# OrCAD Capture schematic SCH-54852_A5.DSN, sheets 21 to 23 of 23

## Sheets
21 C-16 EXPI/IMU/ADC: size C
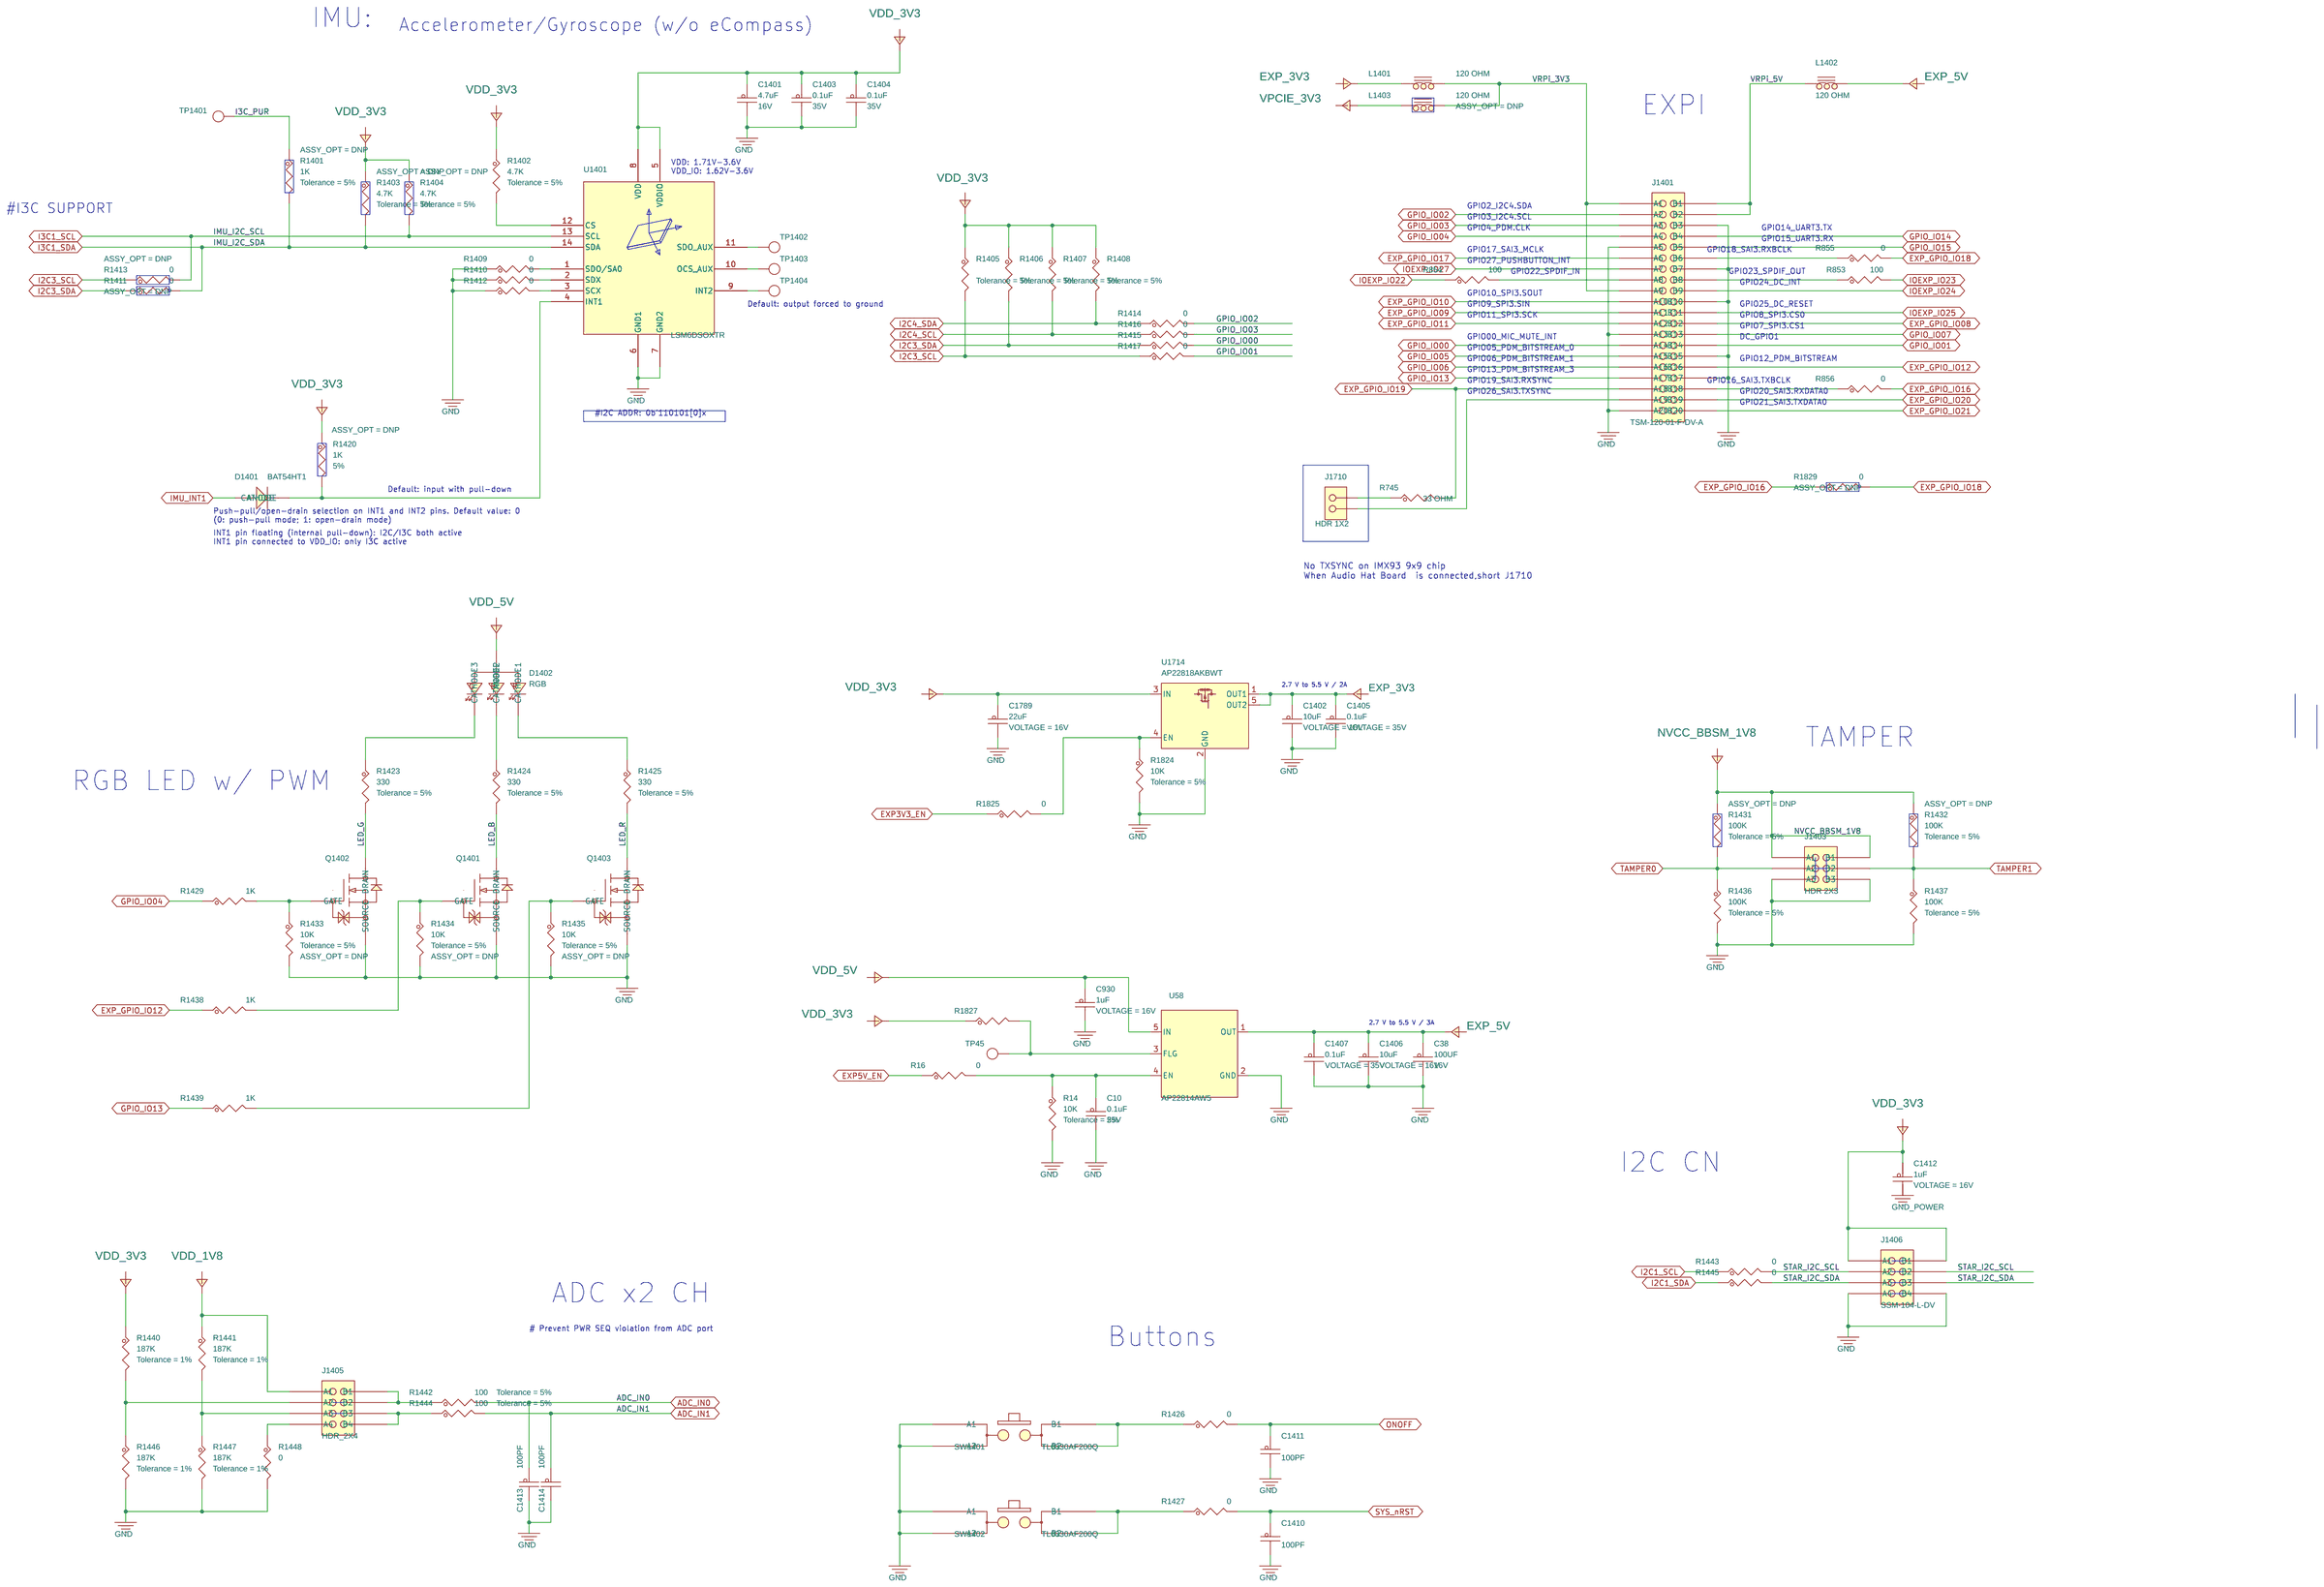
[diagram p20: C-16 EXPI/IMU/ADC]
22 C-08 eMMC/MicroSD: size C
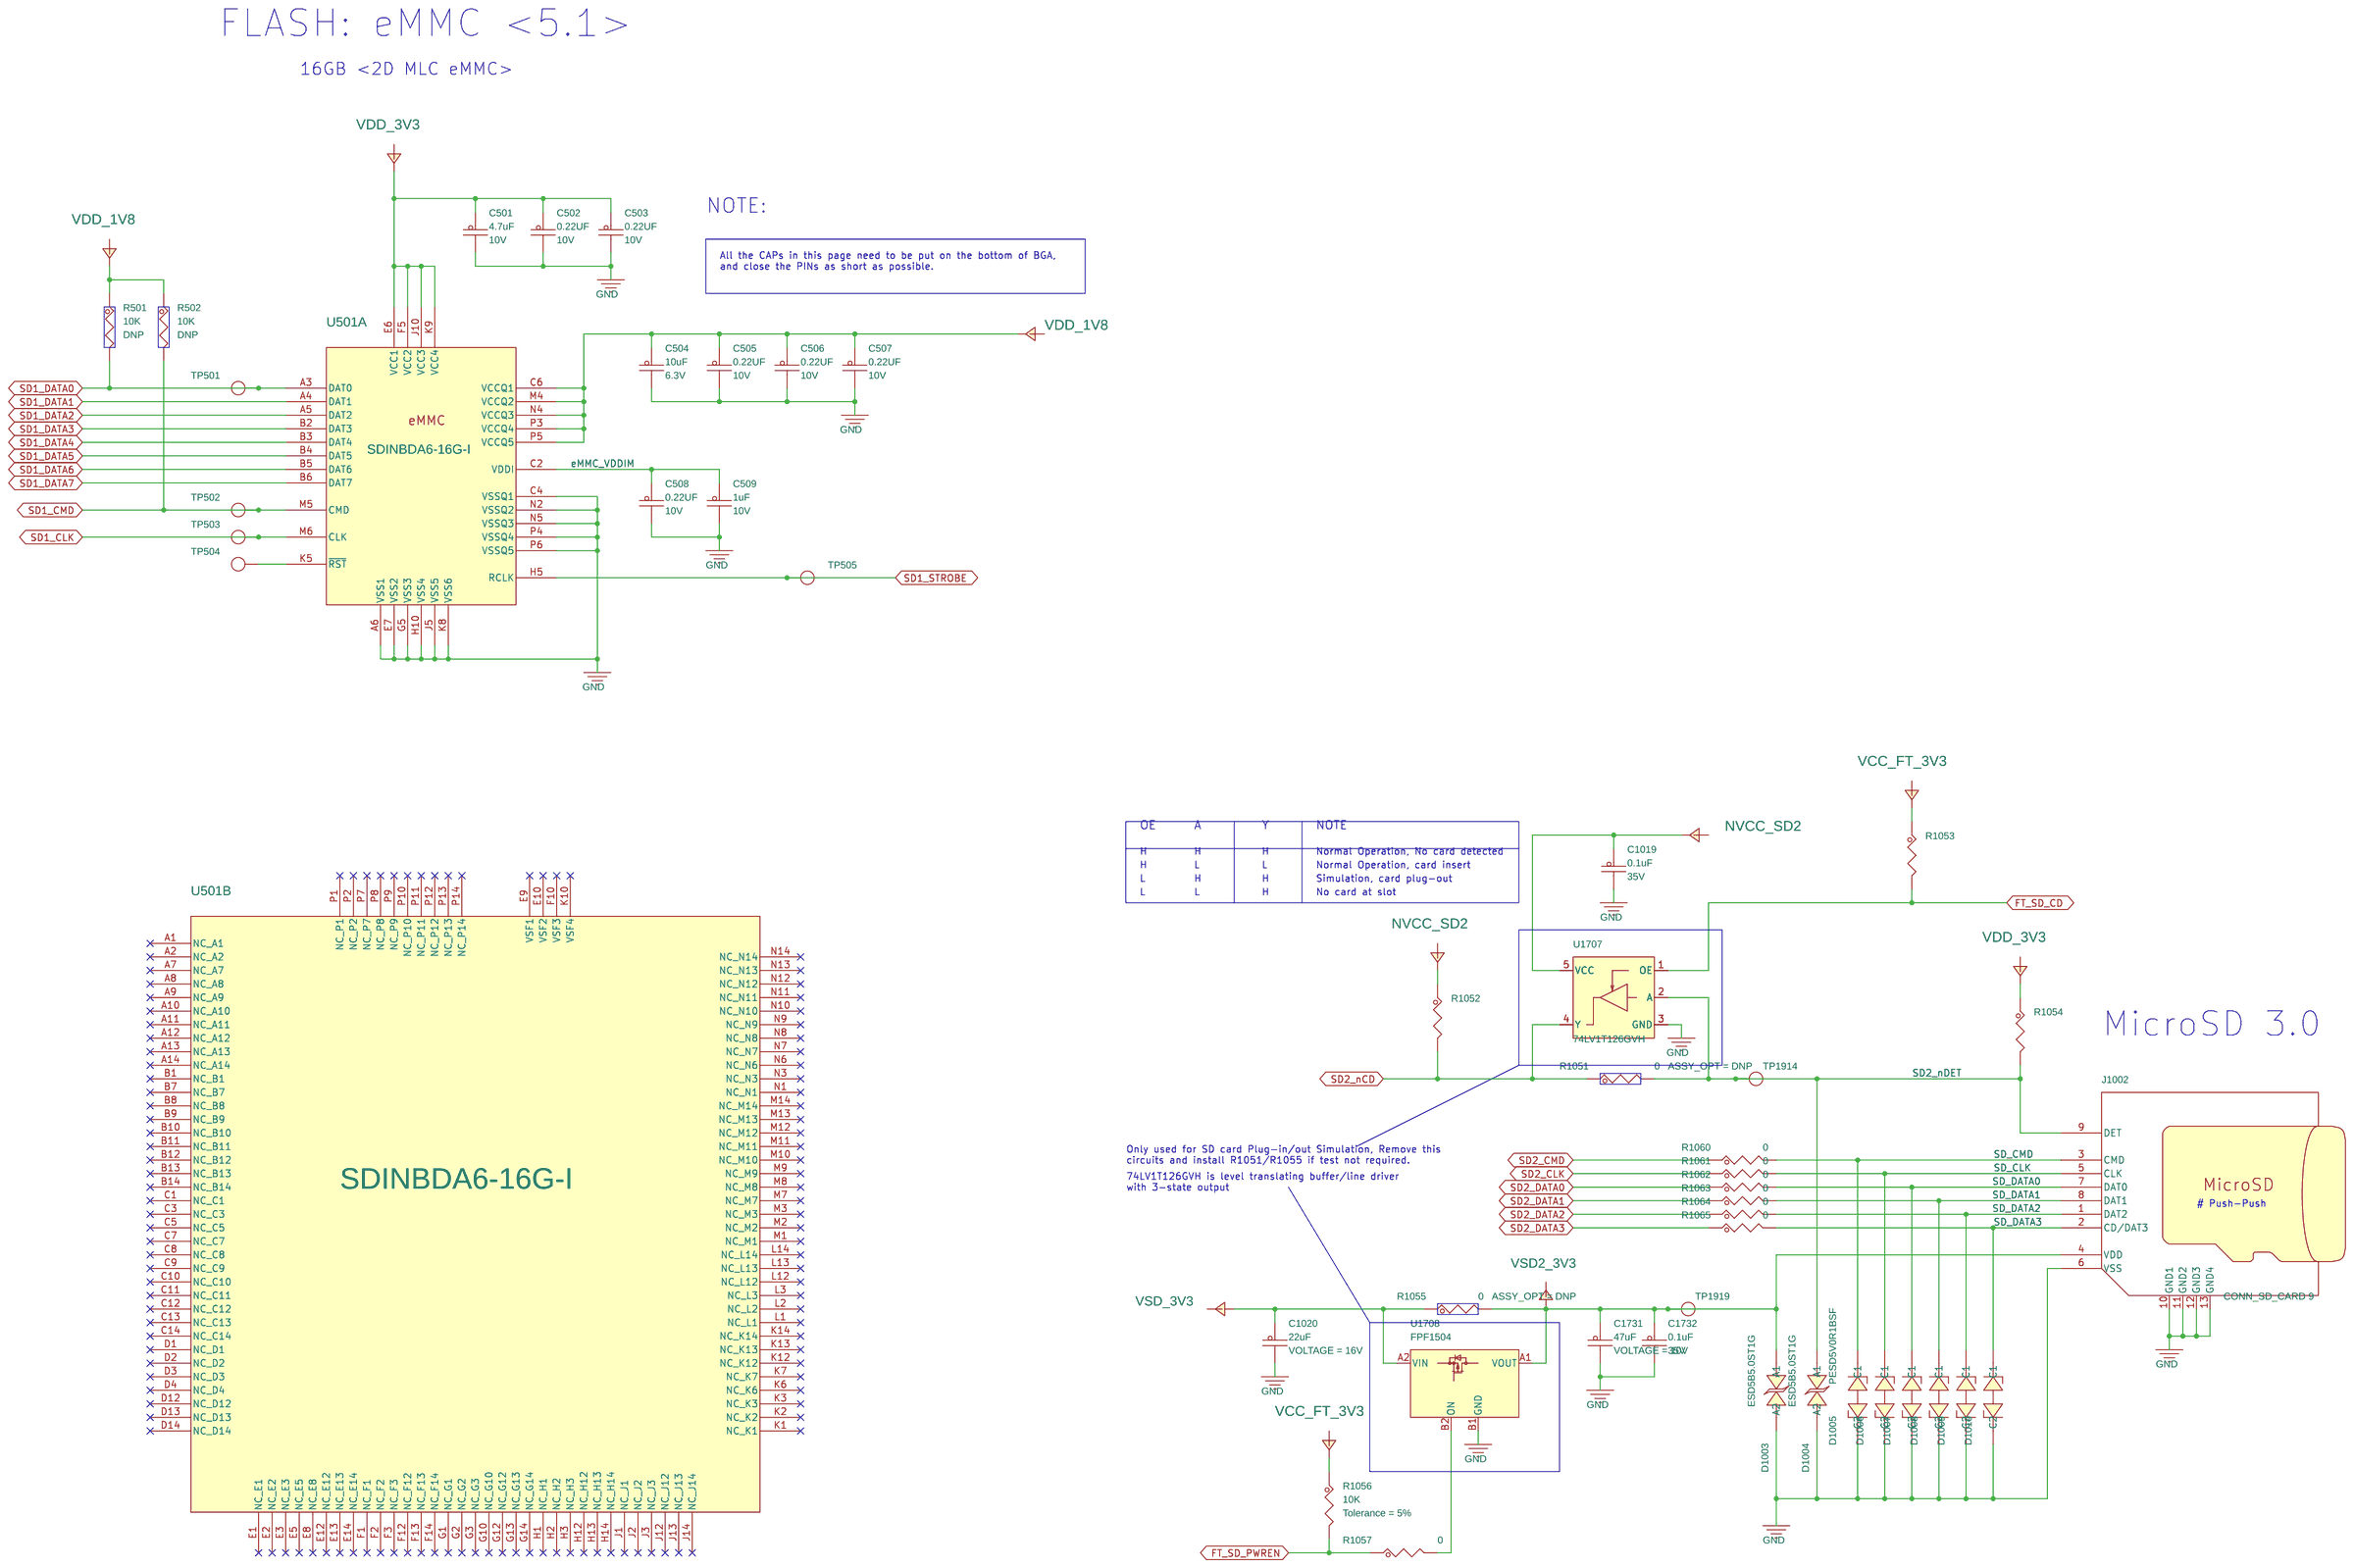
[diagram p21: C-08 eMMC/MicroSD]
23 C-19 BOOT CFG/PDM: size C
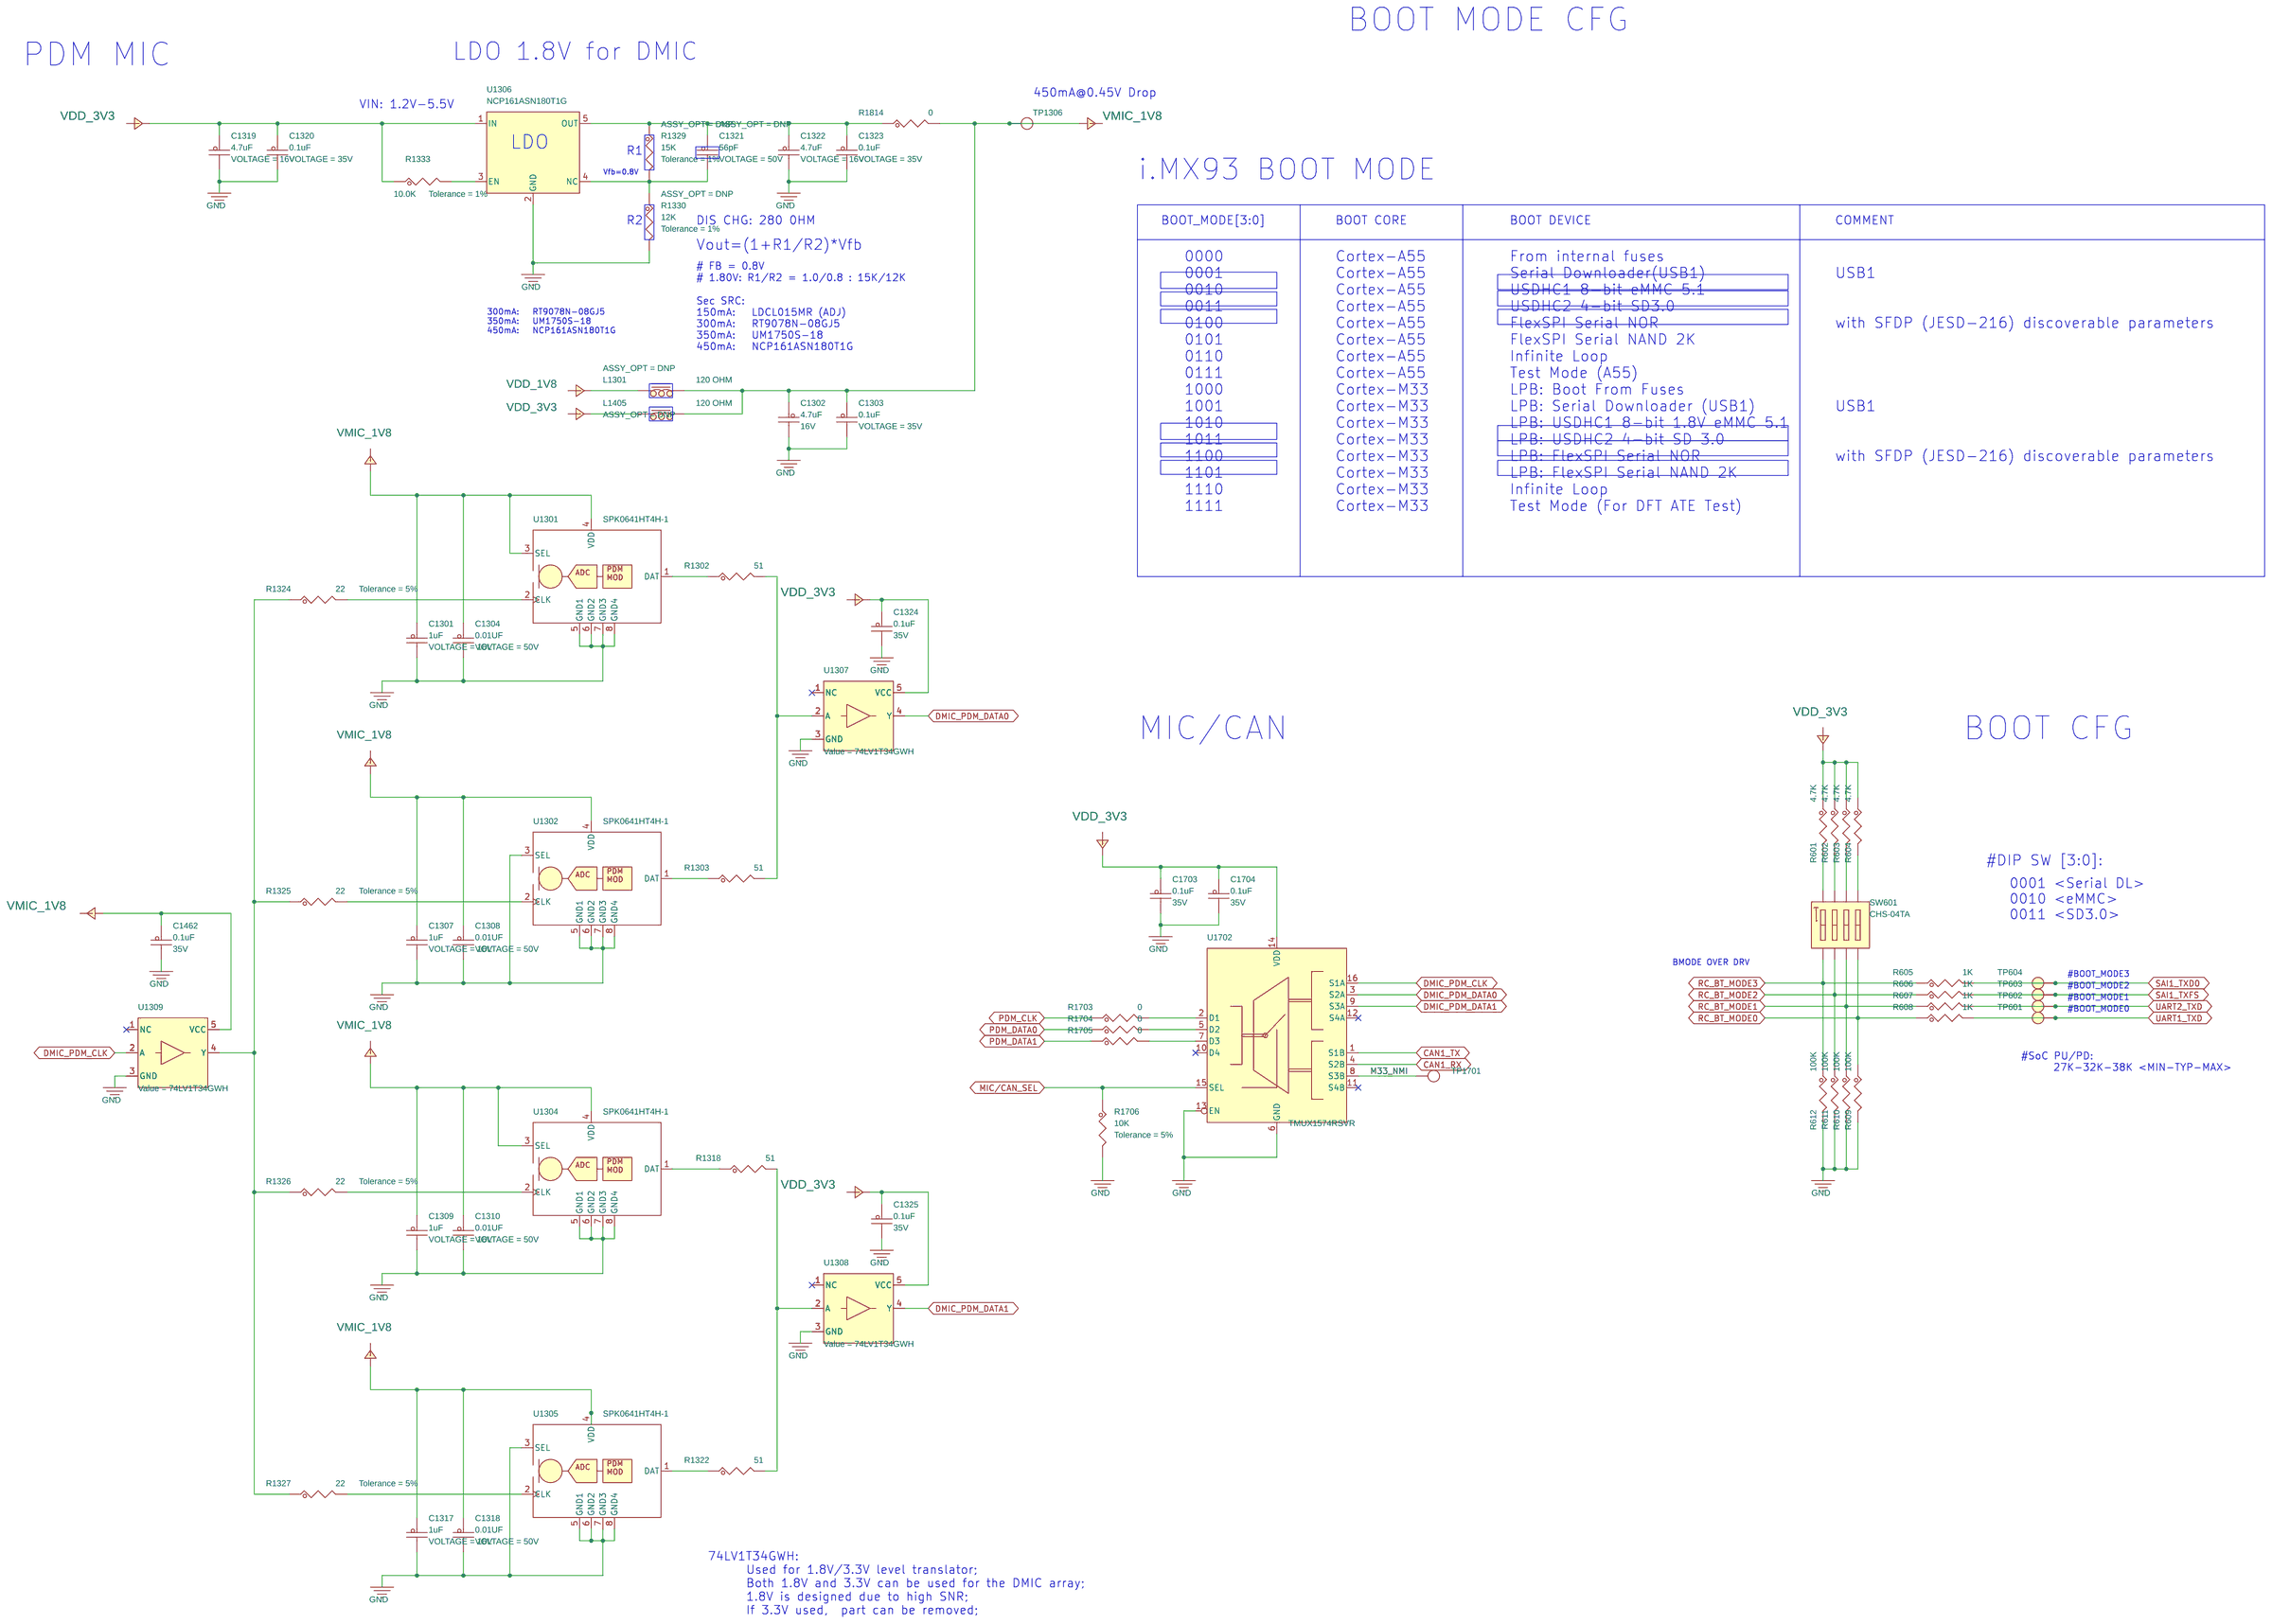
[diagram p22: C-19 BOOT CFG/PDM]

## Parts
sheet C-08 eMMC/MicroSD
C501  4.7uF  [cc0402_tol0p15]
C502  0.22UF  [0201_CC]
C503  0.22UF  [0201_CC]
C504  10uF  [0402_CC]
C505  0.22UF  [0201_CC]
C506  0.22UF  [0201_CC]
C507  0.22UF  [0201_CC]
C508  0.22UF  [0201_CC]
C509  1uF  [0201_CC]
C1019  0.1uF  [CC0402_25]
C1020  22uF  [CC0805_OV]
C1731  47uF  [0805_CC]
C1732  0.1uF  [CC0402_25]
D1003  ESD5B5.0ST1G  [diode2_sod523]
D1004  ESD5B5.0ST1G  [diode2_sod523]
D1005  PESD5V0R1BSF  [dsn0603-2]
D1006  PESD5V0R1BSF  [dsn0603-2]
D1007  PESD5V0R1BSF  [dsn0603-2]
D1008  PESD5V0R1BSF  [dsn0603-2]
D1009  PESD5V0R1BSF  [dsn0603-2]
D1010  PESD5V0R1BSF  [dsn0603-2]
J1002  CONN_SD_CARD 9  [con9_sdcard_1p1mm]
R501  10K  [0402_CC]
R502  10K  [0402_CC]
R1051  0  [0402_CC]
R1052  10K  [0402_CC]
R1053  10K  [0402_CC]
R1054  10K  [0402_CC]
R1055  0  [0603_CC]
R1056  10K  [0402_CC]
R1057  0  [0402_CC]
R1060  0  [0402_CC]
R1061  0  [0402_CC]
R1062  0  [0402_CC]
R1063  0  [0402_CC]
R1064  0  [0402_CC]
R1065  0  [0402_CC]
TP501  TPAD_020  [tpad_020]
TP502  TPAD_020  [tpad_020]
TP503  TPAD_020  [tpad_020]
TP504  TPAD_015  [TPAD_015]
TP505  TPAD_020  [tpad_020]
TP1914  TPAD_050  [TPAD_050]
TP1919  TPAD_050  [TPAD_050]
U501  SDINBDA6-16G-I  [fbga153_0p5_11p5x13]  (sections A,B)
U1707  74LV1T126GVH  [sot753_5p_1p7x3p1mm]
U1708  FPF1504  [wlcsp4_0p5_0p99x0P99]
sheet C-16 EXPI/IMU/ADC
C10  0.1uF  [0402_CC]
C38  100UF  [1210_CC]
C930  1uF  [CC0402_25]
C1401  4.7uF  [CC0603_OV]
C1402  10uF  [CC0603_OV]
C1403  0.1uF  [CC0402_25]
C1404  0.1uF  [CC0402_25]
C1405  0.1uF  [CC0402_25]
C1406  10uF  [CC0603_OV]
C1407  0.1uF  [CC0402_25]
C1410  100PF  [CC0402_25]
C1411  100PF  [CC0402_25]
C1412  1uF  [CC0402_25]
C1413  100PF  [CC0402_25]
C1414  100PF  [CC0402_25]
C1789  22uF  [CC0805_OV]
D1401  BAT54HT1  [SOD323]
D1402  RGB  [led4_3p4x3_sm]
J1401  TSM-120-01-F-DV-A  [hdr220_tsm_a_sm]
J1403  HDR 2X3  [hdr203_tmm_210h]
J1405  HDR_2X4  [HDR204_TMM_SM]
J1406  SSM-104-L-DV  [con_2x4_skt_100_sm]
J1710  HDR 1X2  [hdr102_tmm]
L1401  120 OHM  [IND_0603]
L1402  120 OHM  [IND_0603]
L1403  120 OHM  [IND_0603]
Q1401  NX3008NBKW,115  [sc70_3]
Q1402  NX3008NBKW,115  [sc70_3]
Q1403  NX3008NBKW,115  [sc70_3]
R14  10K  [0402_CC]
R16  0  [0402_CC]
R745  33 OHM  [RC0402_25]
R853  100  [RC0402_25]
R854  100  [RC0402_25]
R855  0  [0402_CC]
R856  0  [0402_CC]
R1401  1K  [0402_CC]
R1402  4.7K  [RC0402_25]
R1403  4.7K  [RC0402_25]
R1404  4.7K  [RC0402_25]
R1405  2.2K  [0402_CC]
R1406  2.2K  [0402_CC]
R1407  2.2K  [0402_CC]
R1408  2.2K  [0402_CC]
R1409  0  [0402_CC]
R1410  0  [0402_CC]
R1411  0  [0402_CC]
R1412  0  [0402_CC]
R1413  0  [0402_CC]
R1414  0  [0402_CC]
R1415  0  [0402_CC]
R1416  0  [0402_CC]
R1417  0  [0402_CC]
R1420  1K  [0402_CC]
R1423  330  [RC0402_25]
R1424  330  [RC0402_25]
R1425  330  [RC0402_25]
R1426  0  [0402_CC]
R1427  0  [0402_CC]
R1429  1K  [0402_CC]
R1431  100K  [0402_CC]
R1432  100K  [0402_CC]
R1433  10K  [0402_CC]
R1434  10K  [0402_CC]
R1435  10K  [0402_CC]
R1436  100K  [0402_CC]
R1437  100K  [0402_CC]
R1438  1K  [0402_CC]
R1439  1K  [0402_CC]
R1440  187K  [0402_CC]
R1441  187K  [0402_CC]
R1442  100  [RC0402_25]
R1443  0  [0402_CC]
R1444  100  [RC0402_25]
R1445  0  [0402_CC]
R1446  187K  [0402_CC]
R1447  187K  [0402_CC]
R1448  0  [0402_CC]
R1824  10K  [0402_CC]
R1825  0  [0402_CC]
R1827  10K  [0402_CC]
R1829  0  [0402_CC]
SW1401  TL6330AF200Q  [sw4_spst_4p6x2p8_sm]
SW1402  TL6330AF200Q  [sw4_spst_4p6x2p8_sm]
TP45  TPAD_050  [TPAD_050]
TP1401  TPAD_020  [tpad_020]
TP1402  TEST POINT  [tp_th_018]
TP1403  TEST POINT  [tp_th_018]
TP1404  TEST POINT  [tp_th_018]
U58  AP22814AW5  [sot25]
U1401  LSM6DSOXTR  [lga14_0p5_3x2p5]
U1714  AP22818AKBWT  [sot23-5]
sheet C-19 BOOT CFG/PDM
C1301  1uF  [CC0402_25]
C1302  4.7uF  [CC0603_OV]
C1303  0.1uF  [CC0402_25]
C1304  0.01UF  [0402_CC]
C1307  1uF  [CC0402_25]
C1308  0.01UF  [0402_CC]
C1309  1uF  [CC0402_25]
C1310  0.01UF  [0402_CC]
C1317  1uF  [CC0402_25]
C1318  0.01UF  [0402_CC]
C1319  4.7uF  [CC0603_OV]
C1320  0.1uF  [0201_CC]
C1321  56pF  [CC0402_25]
C1322  4.7uF  [CC0603_OV]
C1323  0.1uF  [0201_CC]
C1324  0.1uF  [CC0402_25]
C1325  0.1uF  [CC0402_25]
C1462  0.1uF  [CC0402_25]
C1703  0.1uF  [CC0402_25]
C1704  0.1uF  [CC0402_25]
L1301  120 OHM  [IND_0603]
L1405  120 OHM  [IND_0603]
R601  4.7K  [RC0402_25]
R602  4.7K  [RC0402_25]
R603  4.7K  [RC0402_25]
R604  4.7K  [RC0402_25]
R605  1K  [0402_CC]
R606  1K  [0402_CC]
R607  1K  [0402_CC]
R608  1K  [0402_CC]
R609  100K  [0402_CC]
R610  100K  [0402_CC]
R611  100K  [0402_CC]
R612  100K  [0402_CC]
R1302  51  [0402_CC]
R1303  51  [0402_CC]
R1318  51  [0402_CC]
R1322  51  [0402_CC]
R1324  22  [0402_CC]
R1325  22  [0402_CC]
R1326  22  [0402_CC]
R1327  22  [0402_CC]
R1329  15K  [RC0402_25]
R1330  12K  [RC0402_25]
R1333  10.0K  [0201_CC]
R1703  0  [0402_CC]
R1704  0  [0402_CC]
R1705  0  [0402_CC]
R1706  10K  [0402_CC]
R1814  0  [0402_CC]
SW601  CHS-04TA  [sw_chs_04_a]
TP601  TP_35MIL  [testpoint_35mil]
TP602  TP_35MIL  [testpoint_35mil]
TP603  TP_35MIL  [testpoint_35mil]
TP604  TP_35MIL  [testpoint_35mil]
TP1306  TPAD_020  [tpad_020]
TP1701  TPAD_050  [TPAD_050]
U1301  SPK0641HT4H-1  [lga8_3p1x4p1mm_spk0641]
U1302  SPK0641HT4H-1  [lga8_3p1x4p1mm_spk0641]
U1304  SPK0641HT4H-1  [lga8_3p1x4p1mm_spk0641]
U1305  SPK0641HT4H-1  [lga8_3p1x4p1mm_spk0641]
U1306  NCP161ASN180T1G  [SOT-23-5]
U1307  74LV1T34GWH  [sc70-5]
U1308  74LV1T34GWH  [sc70-5]
U1309  74LV1T34GWH  [sc70-5]
U1702  TMUX1574RSVR  [pqfn16_0p4_2p65x1p85]

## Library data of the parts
C501 = CAP_NP: CAP CER 4.7uF 10V 10% X5R 0402; AGILE_PN: 150-80044; CAD_APPROVED: Yes; FPLIST: cc0402_tol0p15,cc0402_tol0p15_ov,0402_cc_nsp; HEIGHT: 0.65MM; MFG_NAME01: SAMSUNG ELECTRO MECHANICS; MFG_PN01: CL05A475KP5NRNC; ROHS: Yes; Tolerance: 10%; VOLTAGE: 10V
C502 C503 C505-C508 = CAP_NP: CAP CER 0.22UF 10V 20% X5R 0201; AGILE_PN: 150-78815; CAD_APPROVED: Yes; FPLIST: CC0201,CC0201_HD,0201_CC; HEIGHT: 0.33MM; MFG_NAME01: Taiyo Yuden; MFG_PN01: LMK063BJ224MP-F; ROHS: Yes; Tolerance: 20%; VOLTAGE: 10V
C504 = CAP_NP: CAP CER 10UF 6.3V 20% X5R 0402; AGILE_PN: 150-79163; CAD_APPROVED: Yes; FPLIST: CC0402_25,CC0402_HD,0402_CC; HEIGHT: 0.65 MM; MFG_NAME01: SAMSUNG ELECTRO MECHANICS; MFG_PN01: CL05A106MQ5NUNC; ROHS: Yes; Tolerance: 20%; VOLTAGE: 6.3V
C509 = CAP_NP: CAP CER 1.0uF 10V 10% X5R 0201; AGILE_PN: 150-81088; CAD_APPROVED: Yes; FPLIST: CC0201,CC0201_HD,0201_CC,cc_0201_cir; HEIGHT: 0.35MM; MFG_NAME01: SAMSUNG ELECTRO MECHANICS; MFG_PN01: CL03A105KP3NSNC; Package Size: 0201 (0603 Metric); Package Type: SMD/SMT; ROHS: Yes; Temp Range: -55°C to 85°C; Tolerance: 10%; VOLTAGE: 10V
C1019 C1303 C1324 C1325 C1405 C1407 C1462 C1703 C1704 C1732 = CAP_NP: CAP CER 0.1UF 35V 10% X5R 0402; AGILE_PN: 150-78506; CAD_APPROVED: Yes; FPLIST: CC0402_25,CC0402_HD,0402_CC,capc0402_l; HEIGHT: 0.55MM; MFG_NAME01: TAIYO YUDEN; MFG_PN01: GMK105BJ104KV-F; ROHS: Yes; Tolerance: 10%; VOLTAGE: 35V
C1020 C1789 = CAP_NP: CAP CER 22UF 16V 20% X5R 0805; AGILE_PN: 150-81221; CAD_APPROVED: Yes; FPLIST: CC0805_OV,CC0805,0805_CC; HEIGHT: 1.45MM; MFG_NAME01: TDK Corporation; MFG_PN01: C2012X5R1C226M125AC; ROHS: Yes; Tolerance: 20%; VOLTAGE: 16V
C1731 = CAP_NP: CAP CER 47uF 10V 20% X5R 0805; AGILE_PN: 150-78979; CAD_APPROVED: Yes; FPLIST: CC0805_OV,CC0805,0805_CC; HEIGHT: 1.45 MM; MFG_NAME01: TDK; MFG_PN01: C2012X5R1A476M125AC; ROHS: Yes; Tolerance: 20%; VOLTAGE: 10V
D1003 D1004 = DIODE_TVS_BIDIR: DIODE SUPPRESSOR 16A@30NS 5V@1UA SOD-523; AGILE_PN: 480-76937; CAD_APPROVED: Yes; HEIGHT: 0.7MM; MFG_NAME01: ON SEMICONDUCTOR
D1005-D1010 = DIODE_BIDIR: DIODE TVS 5VWM 9.2VC DSN0603-2; AGILE_PN: 480-79664; CAD_APPROVED: Yes; HEIGHT: 0.32MM; MFG_NAME01: NEXPERIA; MFG_PN01: PESD5V0R1BSFYL
J1002 = CONN_MICRO_SDCARD: CON 9 SD CARD PUSH SMT 1.1MM SP 81H AU; AGILE_PN: 211-79878; CAD_APPROVED: Yes; HEIGHT: 2.05 MM; MFG_NAME01: SHENZHEN ATOM TECHNOLOGY CO.,LTD; MFG_PN01: MR01A-01202; Package Type: SMT; ROHS: Yes
R501 R502 R1433-R1435 = RES: RES MF 10K 1/16W 5% 0402; AGILE_PN: 470-75557; ASSY_OPT: DNP; CAD_APPROVED: Yes; FPLIST: RC0402_25,RC0402_HD,0402_CC; HEIGHT: 0.4 MM; MFG_NAME01: VISHAY INTERTECHNOLOGY; MFG_PN01: CRCW040210K0JNED; ROHS: Yes; Tolerance: 5%
R1051 R1411 R1413 R1829 = RES: RES MF ZERO OHM 1/16W 5% 0402; AGILE_PN: 470-75394; ASSY_OPT: DNP; CAD_APPROVED: Yes; FPLIST: RC0402_25,RC0402_HD,RC0402_X2,0402_CC; HEIGHT: 0.45 MM; MFG_NAME01: YAGEO AMERICA; MFG_PN01: RC0402JR-070RL; ROHS: Yes; Tolerance: 5%; VOLTAGE: 1/16W
R14 R1052-R1054 R1056 R1706 R1824 R1827 = RES: RES MF 10K 1/16W 5% 0402; AGILE_PN: 470-75557; CAD_APPROVED: Yes; FPLIST: RC0402_25,RC0402_HD,0402_CC; HEIGHT: 0.4 MM; MFG_NAME01: VISHAY INTERTECHNOLOGY; MFG_PN01: CRCW040210K0JNED; ROHS: Yes; Tolerance: 5%
R1055 = RES: RES MF ZERO OHM 1/10W -- 0603; AGILE_PN: 470-80866; ASSY_OPT: DNP; CAD_APPROVED: Yes; FPLIST: RC0603_OV,RC0603,R603-X2,0603_CC,IND_0603HP_NSP,CC0603_OV_NSP; HEIGHT: 0.6MM; MFG_NAME01: WALSIN TECHNOLOGY CORP.; MFG_PN01: WR06X000PTL; ROHS: Yes; Temp Range: –55 °C to +155 °C
R16 R1057 R1825 = RES: RES MF ZERO OHM 1/16W 5% 0402; AGILE_PN: 470-75394; CAD_APPROVED: Yes; FPLIST: RC0402_25,RC0402_HD,RC0402_X2,0402_CC; HEIGHT: 0.45 MM; MFG_NAME01: ROHM; MFG_PN01: MCR01MZPJ000; ROHS: Yes; Tolerance: 5%; VOLTAGE: 1/16W
R855 R856 R1060-R1065 R1409 R1410 R1412 R1414-R1417 R1426 R1427 R1443 R1445 R1448 = RES: RES MF ZERO OHM 1/16W 5% 0402; AGILE_PN: 470-75394; CAD_APPROVED: Yes; FPLIST: RC0402_25,RC0402_HD,RC0402_X2,0402_CC; HEIGHT: 0.45 MM; MFG_NAME01: YAGEO AMERICA; MFG_PN01: RC0402JR-070RL; ROHS: Yes; Tolerance: 5%; VOLTAGE: 1/16W
TP501-TP503 TP505 TP1306 TP1401 = TESTLOOP: TEST POINT PAD 0.5MM DIA SMT, NO PART TO ORDER; AGILE_PN: 211-77484; ASSY_OPT: DNP; CAD_APPROVED: Yes; HEIGHT: 0.1MM; ROHS: Yes
TP504 = TESTLOOP: TEST POINT PAD 15MIL DIA SMT, NO PART TO ORDER; AGILE_PN: 211-76645; ASSY_OPT: DNP; CAD_APPROVED: Yes; HEIGHT: 0.1MM; MFG_NAME01: NOTACOMPONENT; MFG_PN01: NOTACOMPONENT; ROHS: Yes
TP1701 TP1914 TP1919 = TESTLOOP: TEST POINT PAD 50MIL DIA SMT, NO PART TO ORDER; AGILE_PN: 211-76644; ASSY_OPT: DNP; CAD_APPROVED: Yes; HEIGHT: 0.1MM; MFG_NAME01: NOTACOMPONENT; MFG_PN01: NOTACOMPONENT; ROHS: Yes
U501 = SDINBDA6_32G_I_VFBGA_153P: IC MEM NAND FLASH 16GB MMC 5.1 CTLR 2.7-3.6V FBGA153; AGILE_PN: 342-00870; CAD_APPROVED: Yes; HEIGHT: 1MM; MFG_NAME01: SANDISK CORPORATION; ROHS: Yes; Temp Range: -25°C to 85°C
U1707 = 74LV1T126GVH: IC VXLTR 1BIT BUF DRV 1.6-5.5V SOT753; 3D_Mechanical_Footprint_File: ftp://fcl.am.freescale.net/ALLEGRO/step/sot753_5p_1p7x3p1mm.STEP; AGILE_PN: 312-83148; CAD_APPROVED: Yes; HEIGHT: 1.1MM; MFG_NAME01: Nexperia; Package Size: SC-74A-5; ROHS: Yes; Temp Range: -40°C to +125°C; VOLTAGE: 1.6-5.5V
U1708 = FPF1504UCX_CSP4_A: IC LOAD SW 15mOHM PMOS 1-3.6V WLCSP4; 3D_Mechanical_Footprint_File: ftp://fcl.am.freescale.net/ALLEGRO/step/wlcsp4_0p5_0p99x0P99.STEP; AGILE_PN: 315-80912; CAD_APPROVED: Yes; HEIGHT: 0.625MM; MFG_NAME01: FAIRCHILD; MFG_PN01: FPF1504UCX; ROHS: Yes; VOLTAGE: 1.0-3.6V
C10 = CAP_NP: CAP CER 0.1UF 25V 10% X5R 0402; AGILE_PN: 150-78633; CAD_APPROVED: Yes; FPLIST: CC0402_25,CC0402_HD,0402_CC; HEIGHT: 0.55MM; MFG_NAME01: YAGEO AMERICA; MFG_PN01: CC0402KRX5R8BB104; Package Size: 0402; ROHS: Yes; Tolerance: 10%; VOLTAGE: 25V
C38 = CAP_NP: CAP CER 100uF 16V 20% X5R 1210; AGILE_PN: 150-79142; CAD_APPROVED: Yes; FPLIST: CC1210,1210_CC; HEIGHT: 2.8MM; MFG_NAME01: TAIYO YUDEN; MFG_PN01: EMK325ABJ107MM-T; Package Size: 1210; ROHS: Yes; Tolerance: 20%; VOLTAGE: 16V
C930 = CAP_NP: CAP CER 1uF 16V 10% X5R 0402; AGILE_PN: 150-78973; CAD_APPROVED: Yes; FPLIST: CC0402_25,CC0402_HD,0402_CC,capc0402_l; HEIGHT: 0.55 MM; MFG_NAME01: YAGEO; MFG_PN01: CC0402KRX5R7BB105; ROHS: Yes; Tolerance: 10%; VOLTAGE: 16V
C1401 = CAP_NP: CAP CER 4.7uF 16V 10% X5R 0603; AGILE_PN: 150-80061; CAD_APPROVED: Yes; EN: 102-1-01650; FPLIST: CC0603_OV,CC0603,cc0603_0805_nsp,0603_CC_NSP; HEIGHT: 0.95MM; MFG_NAME01: MURATA; MFG_PN01: GRM188R61C475KE11D; ROHS: Yes; TOL: 10%; Temp Range: -55°C to + 85°C; VOLTAGE: 16V
C1402 C1406 = CAP_NP: CAP CER 10uF 16V 20% X5R 0603; AGILE_PN: 150-80336; CAD_APPROVED: Yes; FPLIST: CC0603_OV,CC0603,0603_CC_NSP; HEIGHT: 1MM; LEAD_FREE: YES; MFG_NAME01: MURATA; MFG_PN01: GRM188R61C106MA73D; Package Size: 0603; Package Type: SMD; ROHS: Yes; Temp_Range: -55°C ~ 85°C; Tolerance: 20%; VOLTAGE: 16V
C1403 C1404 = CAP_NP: CAP CER 0.1UF 35V 10% X5R 0402; AGILE_PN: 150-78506; CAD_APPROVED: Yes; EN: 102-1-02300; FPLIST: CC0402_25,CC0402_HD,0402_CC,capc0402_l; HEIGHT: 0.55MM; MFG_NAME01: TAIYO YUDEN; MFG_PN01: GMK105BJ104KV-F; ROHS: Yes; TOL: 10%; Tolerance: 10%; VOLTAGE: 35V
C1410 C1411 C1413 C1414 = CAP_NP: CAP CER 100PF 16V 5% C0G 0402; AGILE_PN: 150-75721; CAD_APPROVED: Yes; FPLIST: CC0402_25,CC0402_HD,0402_CC,capc0402_l; HEIGHT: 0.55MM; MFG_NAME01: KEMET; MFG_PN01: C0402C101J4GAC; Package Size: 0402; ROHS: Yes; Tolerance: 5%; VOLTAGE: 16V
C1412 = CAP_NP: CAP CER 1uF 16V 10% X5R 0402; AGILE_PN: 150-78973; CAD_APPROVED: Yes; FPLIST: CC0402_25,CC0402_HD,0402_CC,capc0402_l; HEIGHT: 0.55 MM; MFG_NAME01: YAGEO; MFG_PN01: CC0402KRX5R7BB105; ROHS: Yes; SIGNAL_MODEL: DEFAULT_CAPACITOR_1e+06pF_2_1; TOL: 10%; Tolerance: 10%; VOLTAGE: 16V; voltage rating: 10V
D1401 = DIODE: DIODE SCH 30V 200MA -- SOD323; AGILE_PN: 480-30039; CAD_APPROVED: Yes; HEIGHT: 1.15MM; MFG_NAME01: ON SEMICONDUCTOR; MFG_PN01: BAT54HT1G
D1402 = LED_GPLY6900: LED RGB MULTI 20MA SMT; AGILE_PN: 370-76731; CAD_APPROVED: Yes; HEIGHT: 2.04 MM; MFG_NAME01: EVERLIGHT INTERNATIONAL CORPORATION; MFG_PN01: 67-03A/R6GHBHW-A01/2T/MS; VOLTAGE: 1.7-3.7V
J1401 = CONN_HDR_20X2: HDR 2X20 SMT 2.54MM CTR 395H AU; 3D_Mechanical_Footprint_File: ftp://fcl.am.freescale.net/ALLEGRO/step/hdr220_tsm_a_sm.step; AGILE_PN: 211-80156; CAD_APPROVED: Yes; HEIGHT: 10.03MM; MFG_NAME01: SAMTEC; ROHS: Yes; Temp Range: -55°C ~ 125°C
J1403 = CONN_HDR_3X2: HDR 2X3 TH 2MM CTR 217H AU 110L; 3D_Mechanical_Footprint_File: ftp://fcl.am.freescale.net/ALLEGRO/step/hdr203_tmm_210h.STEP; AGILE_PN: 210-77094; CAD_APPROVED: Yes; FPLIST: hdr203_tmm_210h,hdr203_tmm; HEIGHT: 5.33MM; MFG_NAME01: SAMTEC; MFG_PN01: TMM-103-02-G-D; ROHS: Yes
J1405 = CONN_HDR_4X2: HDR 2X4 SMT 78.7MIL CTR 235H AU LOPRO; 3D_Mechanical_Footprint_File: ftp://fcl.am.freescale.net/ALLEGRO/step/hdr204_tmm_sm.STEP; AGILE_PN: 211-75114; CAD_APPROVED: Yes; HEIGHT: 5.97MM; MFG_NAME01: SAMTEC; MFG_PN01: TMM-104-01-S-D-SM; Package Size: SMD-8; Package Type: SMD; ROHS: Yes; Temp Range: -55°C to +125°C
J1406 = CONN_HDR_4X2: CON 2X4 SKT SMT 2.54MM CTR 300H AU; 3D_Mechanical_Footprint_File: ftp://fcl.am.freescale.net/ALLEGRO/step/con_2x4_skt_100_sm.STEP; AGILE_PN: 211-79467; CAD_APPROVED: Yes; HEIGHT: 7.62MM; MFG_NAME01: SAMTEC; ROHS: Yes
J1710 = CONN_HDR_2X1: HDR 1X2 TH 2MM SP 217H AU 110L; AGILE_PN: 210-77112; CAD_APPROVED: Yes; FPLIST: hdr102_tmm,sh_hdr102_tmm_bottom; HEIGHT: 5.2MM; MFG_NAME01: SAMTEC; MFG_PN01: TMM-102-02-G-S; ROHS: Yes
L1401 L1402 = BEAD_0: IND FER BEAD 120OHM@100MHZ 2A 25% 0603; AGILE_PN: 180-78419; CAD_APPROVED: Yes; FPLIST: IND_0603,0603_CC; HEIGHT: 0.95MM; MFG_NAME01: SHENZHEN SUNLORD ELECTRONICS CO., LTD; MFG_PN01: PZ1608U121-2R0TF; ROHS: Yes
L1403 = BEAD_0: IND FER BEAD 120OHM@100MHZ 2A 25% 0603; AGILE_PN: 180-78419; ASSY_OPT: DNP; CAD_APPROVED: Yes; FPLIST: IND_0603,0603_CC; HEIGHT: 0.95MM; MFG_NAME01: SHENZHEN SUNLORD ELECTRONICS CO., LTD; MFG_PN01: PZ1608U121-2R0TF; ROHS: Yes
Q1401-Q1403 = NX3008NBKW_SOT323: TRAN NMOS SW 30V 350mA AEC-Q101 SC-70; AGILE_PN: 480-79736; CAD_APPROVED: Yes; HEIGHT: 1.1MM; MFG_NAME01: NEXPERIA; ROHS: Yes
R745 = RES: RES MF 33 OHM 1/10W 1% AEC-Q200  0402; AGILE_PN: 470-80961; CAD_APPROVED: Yes; FPLIST: RC0402_25,RC0402_HD,0402_CC; HEIGHT: 0.4 MM; MFG_NAME01: PANASONIC; MFG_PN01: ERJ2RKF33R0X; ROHS: Yes; Tolerance: 1%
R853 R854 R1442 R1444 = RES: RES MF 100 OHM 1/16W 5% 0402; AGILE_PN: 470-82142; CAD_APPROVED: Yes; FPLIST: RC0402_25,RC0402_HD,RC0402_X2,0402_CC; HEIGHT: 0.45MM; MFG_NAME01: SMEC; MFG_PN01: RC73L2Z101JTF; ROHS: Yes; Temp Range: -55°C to +175°C; Tolerance: 5%
R1401 R1420 = RES: RES MF 1.0K 1/16W 5% 0402; AGILE_PN: 470-75555; ASSY_OPT: DNP; CAD_APPROVED: Yes; FPLIST: RC0402_25,RC0402_HD,RC0402_X2,0402_CC,CAPC0402_L; HEIGHT: 0.41mm; MFG_NAME01: VISHAY INTERTECHNOLOGY; MFG_PN01: CRCW04021K00JNED; ROHS: Yes; Tolerance: 5%
R601-R604 R1402 = RES: RES MF 4.7K 1/16W 5% 0402; AGILE_PN: 470-75626; CAD_APPROVED: Yes; FPLIST: RC0402_25,RC0402_HD,0402_CC,RC0402_X2; HEIGHT: 0.41mm; MFG_NAME01: NIC COMPONENTS CORP; MFG_PN01: NRCL04J472TRF; ROHS: Yes; Tolerance: 5%
R1403 R1404 = RES: RES MF 4.7K 1/16W 5% 0402; AGILE_PN: 470-75626; ASSY_OPT: DNP; CAD_APPROVED: Yes; FPLIST: RC0402_25,RC0402_HD,0402_CC,RC0402_X2; HEIGHT: 0.41mm; MFG_NAME01: NIC COMPONENTS CORP; MFG_PN01: NRCL04J472TRF; ROHS: Yes; Tolerance: 5%
R1405-R1408 = RES: RES MF 2.2K 1/16W 5% 0402; AGILE_PN: 470-76602; CAD_APPROVED: Yes; FPLIST: RC0402_25,RC0402_HD,0402_CC; HEIGHT: 0.4 MM; MFG_NAME01: YAGEO AMERICA; MFG_PN01: RC0402JR-072K2L; RATING: 1/16W; ROHS: Yes; Tolerance: 5%
R1423-R1425 = RES: RES MF 330 OHM 1/16W 5% 0402; AGILE_PN: 470-82124; CAD_APPROVED: Yes; FPLIST: RC0402_25,RC0402_HD,0402_CC; HEIGHT: 0.4MM; MFG_NAME01: NIC COMPONENTS CORP; MFG_PN01: NRCL04J331TRF; ROHS: Yes; Temp Range: -55 ~ +155; Tolerance: 5%
R1429 R1438 R1439 = RES: RES MF 1.0K 1/16W 5% 0402; AGILE_PN: 470-75555; CAD_APPROVED: Yes; FPLIST: RC0402_25,RC0402_HD,RC0402_X2,0402_CC,CAPC0402_L; HEIGHT: 0.41mm; MFG_NAME01: VISHAY INTERTECHNOLOGY; MFG_PN01: CRCW04021K00JNED; ROHS: Yes; Tolerance: 5%
R1431 R1432 = RES: RES MF 100K 1/16W 5% 0402; AGILE_PN: 470-75597; ASSY_OPT: DNP; CAD_APPROVED: Yes; FPLIST: RC0402_25,RC0402_HD,0402_CC; HEIGHT: 0.40 MM; MFG_NAME01: VENKEL COMPANY; MFG_PN01: CR0402-16W-104JT; ROHS: Yes; Temp Range: -55C to +155C; Temp_Range: -55C to +155C; Tolerance: 5%; VOLTAGE: 50V
R1436 R1437 = RES: RES MF 100K 1/16W 5% 0402; AGILE_PN: 470-75597; CAD_APPROVED: Yes; FPLIST: RC0402_25,RC0402_HD,0402_CC; HEIGHT: 0.40 MM; MFG_NAME01: VENKEL COMPANY; MFG_PN01: CR0402-16W-104JT; ROHS: Yes; Temp Range: -55C to +155C; Temp_Range: -55C to +155C; Tolerance: 5%; VOLTAGE: 50V
R1440 R1441 R1446 R1447 = RES: RES MF 187K 1/16W 1% 0402; AGILE_PN: 470-31090; CAD_APPROVED: Yes; FPLIST: RC0402_25,RC0402_HD,0402_CC; HEIGHT: 0.40 MM; MFG_NAME01: WALSIN TECHNOLOGY CORP.; MFG_PN01: WR04X1873FTL; ROHS: Yes; Temp Range: -55C to +155C; Temp_Range: -55C to +155C; Tolerance: 1%; VOLTAGE: 50V
SW1401 SW1402 = SW_PB_ESW: SW SPST NO TACTILE 50mA 12V SMT; 3D_Mechanical_Footprint_File: ftp://fcl.am.freescale.net/ALLEGRO/step/sw4_spst_4p6x2p8_sm.STEP; AGILE_PN: 510-78339; CAD_APPROVED: Yes; HEIGHT: 1.9MM; MFG_NAME01: E SWITCH; Package Size: 4.6x2.8x1.9mm; ROHS: Yes; Temp Range: -40 to +85C
TP45 = TESTLOOP: TEST POINT PAD 50MIL DIA SMT, NO PART TO ORDER; AGILE_PN: 211-76644; CAD_APPROVED: Yes; HEIGHT: 0.1MM; MFG_NAME01: NOTACOMPONENT; MFG_PN01: NOTACOMPONENT; ROHS: Yes
TP1402-TP1404 = TESTLOOP: TEST POINT PAD 036-018MIL TH, NO PART TO ORDER; AGILE_PN: 280-76691; CAD_APPROVED: Yes; HEIGHT: 0.127MM; MFG_NAME01: NA; MFG_PN01: NO PART TO ORDER1; ROHS: Yes
U58 = AP22816_SOT25_5P: IC USB PWR SW 3A 2.7-5.5V SOT25; 3D_Mechanical_Footprint_File: ftp://fcl.am.freescale.net/ALLEGRO/step/sot25.step; AGILE_PN: TMP-CIP-12027; CAD_APPROVED: Yes; HEIGHT: 1.4MM; MFG_NAME01: DIODES INC; MFG_PN01: AP22814AW5-7; PRE_APN: 315-83844; Package Size: SC-74A, SOT-753; ROHS: Yes; Supply Voltage: Not Required; Temp Range: -40°C to + 85°C; VOLTAGE: 2.7-5.5V
U1401 = LSM6DSO_LGA14P: IC 3D ACCELEROMETER GYRO 1.71-3.6V LGA14; 3D_Mechanical_Footprint_File: ftp://fcl.am.freescale.net/ALLEGRO/step/lga14_0p5_3x2p5.STEP; AGILE_PN: 312-82731; CAD_APPROVED: Yes; HEIGHT: 0.86MM; MFG_NAME01: ST MICROELECTRONICS; Package Size: LGA-14L; ROHS: Yes; Temp Range: -40°C to 85°C
U1714 = AP22818AKB: IC USB POWER SWITCH 2A 2.7-5.5V TSOT25; 3D_Mechanical_Footprint_File: ftp://fcl.am.freescale.net/ALLEGRO/step/sot23-5.STEP; AGILE_PN: 315-83467; CAD_APPROVED: Yes; HEIGHT: 1MM; MFG_NAME01: DIODES INC; MFG_PN01: AP22818AKBWT-7; ROHS: Yes; Temp Range: -40°C to +85°C; VOLTAGE: 2.7-5.5V
C1301 C1307 C1309 C1317 = CAP_NP: CAP CER 1uF 16V 10% X5R 0402; AGILE_PN: 150-78973; CAD_APPROVED: Yes; FPLIST: CC0402_25,CC0402_HD,0402_CC,capc0402_l; HEIGHT: 0.55 MM; MFG_NAME01: YAGEO; MFG_PN01: CC0402KRX5R7BB105; ROHS: Yes; SIGNAL_MODEL: DEFAULT_CAPACITOR_1e+06pF_2_1; Temp_Range: -55°C to +85°C; Tolerance: 10%; VOLTAGE: 16V
C1302 = CAP_NP: CAP CER 4.7uF 16V 10% X5R 0603; AGILE_PN: 150-80061; CAD_APPROVED: Yes; FPLIST: CC0603_OV,CC0603,cc0603_0805_nsp,0603_CC_NSP; HEIGHT: 0.95MM; MFG_NAME01: MURATA; MFG_PN01: GRM188R61C475KE11D; ROHS: Yes; Temp Range: -55°C to + 85°C; VOLTAGE: 16V
C1304 C1308 C1310 C1318 = CAP_NP: CAP CER 0.01UF 50V 10% X7R 0402; AGILE_PN: 150-30114; CAD_APPROVED: Yes; FPLIST: CC0402_25,CC0402_HD,0402_CC; HEIGHT: 0.74 MM; MFG_NAME01: KEMET; MFG_PN01: C0402C103K5RAC; ROHS: Yes; TOL: 10%; Tolerance: 10%; VOLTAGE: 50V
C1319 C1322 = CAP_NP: CAP CER 4.7uF 16V 20% X5R 0603; AGILE_PN: 150-80930; CAD_APPROVED: Yes; FPLIST: CC0603_OV,CC0603,0603_CC_NSP; HEIGHT: 0.55MM; MFG_NAME01: Murata Electronics; MFG_PN01: GRM185R61C475ME11D; Package Size: 0603 (1608 Metric); Package Type: Surface Mount, MLCC; ROHS: Yes; Rated Voltage: 16V; Tolerance: 20%; VOLTAGE: 16V
C1320 C1323 = CAP_NP: CAP CER 0.1uF 35V 10% X5R 0201; AGILE_PN: 150-79857; CAD_APPROVED: Yes; EN: 102-1-02300; FPLIST: CC0201,CC0201_HD,0201_CC,cc_0201_cir; HEIGHT: 0.33MM; MFG_NAME01: MURATA; MFG_PN01: GRM033R6YA104KE14D; Package Size: 0201; Package Type: SMD; ROHS: Yes; TOL: 10%; Tolerance: 10%; VOLTAGE: 35V
C1321 = CAP_NP: CAP CER 56PF 50V 5% C0G 0402; AGILE_PN: 150-80332; ASSY_OPT: DNP; CAD_APPROVED: Yes; FPLIST: CC0402_25,CC0402_HD,0402_CC,capc0402_l; HEIGHT: 0.55MM; MFG_NAME01: KEMET; MFG_PN01: C0402C560J5GAC; Package Size: 0402; ROHS: Yes; Temp Range: -55C to +125C; Tolerance: 5%; VOLTAGE: 50V
L1301 L1405 = BEAD_0: IND FER BEAD 120OHM@100MHZ 2A 25% 0603; AGILE_PN: 180-78419; ASSY_OPT: DNP; CAD_APPROVED: Yes; FPLIST: IND_0603,0603_CC; HEIGHT: 0.95MM; MFG_NAME01: MURATA; MFG_PN01: BLM18PG121SN1D; ROHS: Yes
R605-R608 = RES: RES MF 1.0K 1/16W 5% 0402; AGILE_PN: 470-75555; CAD_APPROVED: Yes; FPLIST: RC0402_25,RC0402_HD,RC0402_X2,0402_CC,CAPC0402_L; HEIGHT: 0.41mm; MFG_NAME01: VISHAY INTERTECHNOLOGY; MFG_PN01: CRCW04021K00JNED; RATING: 1/16W; ROHS: Yes; Tolerance: 5%
R609-R612 = RES: RES MF 100K 1/16W 5% 0402; AGILE_PN: 470-75597; CAD_APPROVED: Yes; FPLIST: RC0402_25,RC0402_HD,0402_CC; HEIGHT: 0.40 MM; MFG_NAME01: VENKEL COMPANY; MFG_PN01: CR0402-16W-104JT; ROHS: Yes; Temp Range: -55C to +155C; Tolerance: 5%; VOLTAGE: 50V
R1302 R1303 R1318 R1322 = RES: RES MF 51 OHM 1/16W 5% 0402; AGILE_PN: 470-76089; CAD_APPROVED: Yes; FPLIST: RC0402_25,RC0402_HD,0402_CC; HEIGHT: 0.40 MM; MFG_NAME01: YAGEO AMERICA; MFG_PN01: RC0402JR-0751RL; ROHS: Yes; Tolerance: 5%
R1324-R1327 = RES: RES MF 22 OHM 1/16W 5% 0402; AGILE_PN: 470-75605; CAD_APPROVED: Yes; FPLIST: RC0402_25,RC0402_HD,0402_CC; HEIGHT: 0.4MM; MFG_NAME01: BOURNS; MFG_PN01: CR0402-JW-220GLF; ROHS: Yes; Tolerance: 5%
R1329 = RES: RES MF 15K  1/16W 1% 0402; AGILE_PN: 470-30965; ASSY_OPT: DNP; CAD_APPROVED: Yes; FPLIST: RC0402_25,RC0402_HD,0402_CC; HEIGHT: 0.40 MM; MFG_NAME01: WALSIN TECHNOLOGY CORP.; MFG_PN01: WR04X1502FTL; ROHS: Yes; Tolerance: 1%
R1330 = RES: RES MF 12K 1/10W 1% AEC-Q200 0402; AGILE_PN: 470-30955; ASSY_OPT: DNP; CAD_APPROVED: Yes; FPLIST: RC0402_25,RC0402_HD,0402_CC; HEIGHT: 0.40 MM; MFG_NAME01: KOA SPEER; MFG_PN01: RK73H1ETTP1202F; ROHS: Yes; Temp Range: -55C to +155C; Tolerance: 1%; VOLTAGE: 50V
R1333 = RES: RES MF 10.0K 1/20W 1% 0201; AGILE_PN: 470-77702; CAD_APPROVED: Yes; FPLIST: RC0201,0201_CC; HEIGHT: 0.26MM; MFG_NAME01: PANASONIC; MFG_PN01: ERJ-1GNF1002C; ROHS: Yes; Tolerance: 1%; VOLTAGE: 1/20W
R1703-R1705 = RES: RES MF ZERO OHM 1/16W 5% 0402; AGILE_PN: 470-75394; CAD_APPROVED: Yes; FPLIST: RC0402_25,RC0402_HD,RC0402_X2,0402_CC; HEIGHT: 0.45 MM; MFG_NAME01: YAGEO AMERICA; MFG_PN01: RC0402JR-070RL; RATING: 1/16W; ROHS: Yes; Tolerance: 5%; VOLTAGE: 1/16W
R1814 = RES: RES MF ZERO OHM 1/16W 5% 0402; AGILE_PN: 470-75394; CAD_APPROVED: Yes; FPLIST: RC0402_25,RC0402_HD,RC0402_X2,0402_CC; HEIGHT: 0.45 MM; MFG_NAME01: ROHM; MFG_PN01: MCR01MZPJ000; RATING: 1/16W; ROHS: Yes; Tolerance: 5%; VOLTAGE: 1/16W
SW601 = CHS-04TA_SW: SW SPST SLD WSH 25MA 24V DIP-4 SMT; 3D_Mechanical_Footprint_File: ftp://fcl.am.freescale.net/ALLEGRO/step/sw_chs_04_a.step; AGILE_PN: 510-77691; CAD_APPROVED: Yes; HEIGHT: 2.5MM; MFG_NAME01: NIDEC COPAL ELECTRONICS CORP; ROHS: Yes
TP601-TP604 = T_POINT_R: TEST POINT PAD .035 SMT, no part to order; AGILE_PN: 510-75618; ASSY_OPT: DNP; CAD_APPROVED: Yes; HEIGHT: 0.1MM; ROHS: Yes
U1301 U1302 U1304 U1305 = SPK0641HT4H_8P_A: IC MIC MEMS PDM DIGITAL SISONIC -26DB 1.6-3.6V LGA8; AGILE_PN: 510-78247; MFG_NAME01: KNOWLES ACOUSTICS
U1306 = NCP161ASN180T1G_A: IC VREG LDO FIXED 1.8V 450mA 1.9-5.5V SOT23-5; 3D_Mechanical_Footprint_File: ftp://fcl.am.freescale.net/ALLEGRO/step/sot-23-5.STEP; AGILE_PN: 315-83463; CAD_APPROVED: Yes; HEIGHT: 1.3 MM; MFG_NAME01: ONSEMI; ROHS: Yes; Temp Range: -40°C ~ 125°C (TJ); VOLTAGE: 1.9-5.5V
U1307-U1309 = 74LV1T34GWH_TSSOP6: IC BUF NON-INVERT 1.6-5.5V TSSOP5; 3D_Mechanical_Footprint_File: ftp://fcl.am.freescale.net/ALLEGRO/step/sc70-5.STEP; AGILE_PN: 312-83344; CAD_APPROVED: Yes; HEIGHT: 1.1 MM; MFG_NAME01: Nexperia; Package Size: TSSOP-5; ROHS: Yes; Temp Range: -40  °C - 125 °C
U1702 = TMUX1574RSVR_A: IC MUX SW SPDT 1.8V UQFN16; AGILE_PN: 312-82341; CAD_APPROVED: Yes; HEIGHT: 0.55MM; MFG_NAME01: TEXAS INSTRUMENTS; ROHS: Yes; Temp Range: -40C to +125C; VOLTAGE: 1.5-5.5V

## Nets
GND: C10.2 C38.2 C501.2 C502.2 C503.2 C504.2 C505.2 C506.2 C507.2 C508.2 C509.2 C930.2 C1019.2 C1020.2 C1301.2 C1302.2 C1303.2 C1304.2 C1307.2 C1308.2 C1309.2 C1310.2 C1317.2 C1318.2 C1319.2 C1320.2 C1322.2 C1323.2 C1324.2 C1325.2 C1401.2 C1402.2 C1403.2 C1404.2 C1405.2 C1406.2 C1407.2 C1410.2 C1411.2 C1412.2 C1413.2 C1414.2 C1462.2 C1703.2 C1704.2 C1731.2 C1732.2 C1789.2 D1003.2(A2) D1004.2(A2) D1005.2(C2) D1006.2(C2) D1007.2(C2) D1008.2(C2) D1009.2(C2) D1010.2(C2) J1002.6(VSS) J1002.10(GND1) J1002.11(GND2) J1002.12(GND3) J1002.13(GND4) J1401.6(B3) J1401.9(A5) J1401.14(B7) J1401.20(B10) J1401.25(A13) J1401.30(B15) J1401.34(B17) J1401.39(A20) J1403.5(A3) J1403.6(B3) J1406.7(A4) J1406.8(B4) Q1401.2(SOURCE) Q1402.2(SOURCE) Q1403.2(SOURCE) R14.2 R609.2 R610.2 R611.2 R612.2 R1330.2 R1409.1 R1410.1 R1412.1 R1433.2 R1434.2 R1435.2 R1436.2 R1437.2 R1446.2 R1447.2 R1448.2 R1706.2 R1824.2 SW1401.1(A1) SW1401.2(A2) SW1402.1(A1) SW1402.2(A2) U58.2(GND) U501.A6(VSS1) U501.C4(VSSQ1) U501.E7(VSS2) U501.G5(VSS3) U501.H10(VSS4) U501.J5(VSS5) U501.K8(VSS6) U501.N2(VSSQ2) U501.N5(VSSQ3) U501.P4(VSSQ4) U501.P6(VSSQ5) U1301.5(GND1) U1301.6(GND2) U1301.7(GND3) U1301.8(GND4) U1302.3(SEL) U1302.5(GND1) U1302.6(GND2) U1302.7(GND3) U1302.8(GND4) U1304.5(GND1) U1304.6(GND2) U1304.7(GND3) U1304.8(GND4) U1305.3(SEL) U1305.5(GND1) U1305.6(GND2) U1305.7(GND3) U1305.8(GND4) U1306.2(GND) U1307.3(GND) U1308.3(GND) U1309.3(GND) U1401.6(GND1) U1401.7(GND2) U1702.6(GND) U1702.13(EN) U1707.3(GND) U1708.B1(GND) U1714.2(GND) ; also on sheet 1 4 5 6 7 8 9 10 11 12 16 17 18 19 20
VCC_FT_3V3: R1053.1 R1056.1 ; also on sheet 5
VDD_1V8: C504.1 C505.1 C506.1 C507.1 J1405.1(A1) L1301.1 R501.1 R502.1 R1441.1 U501.C6(VCCQ1) U501.M4(VCCQ2) U501.N4(VCCQ3) U501.P3(VCCQ4) U501.P5(VCCQ5) ; also on sheet 5 6 7 8 9 12 16 17 18
VDD_3V3: C501.1 C502.1 C503.1 C1319.1 C1320.1 C1324.1 C1325.1 C1401.1 C1403.1 C1404.1 C1412.1 C1703.1 C1704.1 C1789.1 J1406.1(A1) J1406.2(B1) L1405.1 R601.1 R602.1 R603.1 R604.1 R1054.1 R1333.1 R1402.1 R1403.1 R1404.1 R1405.1 R1406.1 R1407.1 R1408.1 R1420.1 R1440.1 R1827.1 U501.E6(VCC1) U501.F5(VCC2) U501.J10(VCC3) U501.K9(VCC4) U1306.1(IN) U1307.5(VCC) U1308.5(VCC) U1401.5(VDDIO) U1401.8(VDD) U1702.14(VDD) U1714.3(IN) ; also on sheet 5 6 7 8 9 10 11 12 16 17 19 20
VDD_5V: C930.1 D1402.2(ANODE) U58.5(IN) ; also on sheet 6 9 10 11 19
ADC_IN0: C1413.1 R1442.2 ; also on sheet 1
ADC_IN1: C1414.1 R1444.2 ; also on sheet 1
CAN1_RX: U1702.4(S2B) ; also on sheet 19
CAN1_TX: U1702.1(S1B) ; also on sheet 19
DMIC_PDM_CLK: U1309.2(A) U1702.16(S1A)
DMIC_PDM_DATA0: U1307.4(Y) U1702.3(S2A)
DMIC_PDM_DATA1: U1308.4(Y) U1702.9(S3A)
eMMC_VDDIM: C508.1 C509.1 U501.C2(VDDI)
EXP3V3_EN: R1825.1 ; also on sheet 12
EXP5V_EN: R16.1 ; also on sheet 12
EXP_3V3: C1402.1 C1405.1 L1401.1 U1714.1(OUT1) U1714.5(OUT2)
EXP_5V: C38.1 C1406.1 C1407.1 L1402.2 U58.1(OUT)
EXP_GPIO_IO08: J1401.24(B12) ; also on sheet 12
EXP_GPIO_IO09: J1401.21(A11) ; also on sheet 12
EXP_GPIO_IO10: J1401.19(A10) ; also on sheet 12
EXP_GPIO_IO11: J1401.23(A12) ; also on sheet 12
EXP_GPIO_IO12: J1401.32(B16) R1438.1 ; also on sheet 12
EXP_GPIO_IO16: R856.2 R1829.1 ; also on sheet 12
EXP_GPIO_IO17: J1401.11(A6) ; also on sheet 12
EXP_GPIO_IO18: R855.2 R1829.2 ; also on sheet 12
EXP_GPIO_IO19: J1401.35(A18) R745.2 ; also on sheet 12
EXP_GPIO_IO20: J1401.38(B19) ; also on sheet 12
EXP_GPIO_IO21: J1401.40(B20) ; also on sheet 12
FT_SD_CD: R1053.2 U1707.1(OE) ; also on sheet 5
FT_SD_PWREN: R1056.2 R1057.1 ; also on sheet 5
GPIO_IO00: J1401.27(A14) R1415.2 ; also on sheet 20
GPIO_IO01: J1401.28(B14) R1417.2 ; also on sheet 20
GPIO_IO02: J1401.3(A2) R1414.2 ; also on sheet 20
GPIO_IO03: J1401.5(A3) R1416.2 ; also on sheet 20
GPIO_IO04: J1401.7(A4) R1429.1 ; also on sheet 20
GPIO_IO05: J1401.29(A15) ; also on sheet 20
GPIO_IO06: J1401.31(A16) ; also on sheet 20
GPIO_IO07: J1401.26(B13) ; also on sheet 20
GPIO_IO13: J1401.33(A17) R1439.1 ; also on sheet 20
GPIO_IO14: J1401.8(B4) ; also on sheet 20
GPIO_IO15: J1401.10(B5) ; also on sheet 20
I2C1_SCL: R1443.1 ; also on sheet 6 7 10 12 17 20
I2C1_SDA: R1445.1 ; also on sheet 6 7 10 12 17 20
I2C3_SCL: R1405.2 R1413.1 R1417.1 ; also on sheet 10
I2C3_SDA: R1406.2 R1411.1 R1415.1 ; also on sheet 10
I2C4_SCL: R1407.2 R1416.1 ; also on sheet 10
I2C4_SDA: R1408.2 R1414.1 ; also on sheet 10
I3C1_SCL: R1404.2 R1413.2 U1401.13(SCL) ; also on sheet 19 20
I3C1_SDA: R1401.2 R1403.2 R1411.2 U1401.14(SDA) ; also on sheet 19 20
I3C_PUR: R1401.1 TP1401.1(Pin1)
IMU_INT1: D1401.A(ANODE) ; also on sheet 12
IOEXP_IO22: R854.1
IOEXP_IO23: R853.2
IOEXP_IO24: J1401.18(B9) ; also on sheet 12
IOEXP_IO25: J1401.22(B11) ; also on sheet 12
IOEXP_IO27: J1401.13(A7) ; also on sheet 12
LED_B: Q1401.3(DRAIN) R1424.2
LED_G: Q1402.3(DRAIN) R1423.2
LED_R: Q1403.3(DRAIN) R1425.2
M33_NMI: TP1701.1(Pin1) U1702.8(S3B)
MIC/CAN_SEL: R1706.1 U1702.15(SEL) ; also on sheet 12
NVCC_BBSM_1V8: J1403.1(A1) J1403.2(B1) R1431.1 R1432.1 ; also on sheet 1 16 17
NVCC_SD2: C1019.1 R1052.1 U1707.5(VCC) ; also on sheet 16 17 20
ONOFF: C1411.1 R1426.2 ; also on sheet 1 5
PDM_CLK: R1703.1 ; also on sheet 20
PDM_DATA0: R1704.1 ; also on sheet 20
PDM_DATA1: R1705.1 ; also on sheet 20
RC_BT_MODE0: R608.1 R609.1 SW601.7 ; also on sheet 5
RC_BT_MODE1: R607.1 R610.1 SW601.5 ; also on sheet 5
RC_BT_MODE2: R606.1 R611.1 SW601.3 ; also on sheet 5
RC_BT_MODE3: R605.1 R612.1 SW601.1 ; also on sheet 5
SAI1_TXD0: R605.2 TP604.1(TP) ; also on sheet 7 20
SAI1_TXFS: R606.2 TP603.1(TP) ; also on sheet 7 20
SD1_CLK: TP503.1(Pin1) U501.M6(CLK) ; also on sheet 20
SD1_CMD: R502.2 TP502.1(Pin1) U501.M5(CMD) ; also on sheet 20
SD1_DATA0: R501.2 TP501.1(Pin1) U501.A3(DAT0) ; also on sheet 20
SD1_DATA1: U501.A4(DAT1) ; also on sheet 20
SD1_DATA2: U501.A5(DAT2) ; also on sheet 20
SD1_DATA3: U501.B2(DAT3) ; also on sheet 20
SD1_DATA4: U501.B3(DAT4) ; also on sheet 20
SD1_DATA5: U501.B4(DAT5) ; also on sheet 20
SD1_DATA6: U501.B5(DAT6) ; also on sheet 20
SD1_DATA7: U501.B6(DAT7) ; also on sheet 20
SD1_STROBE: TP505.1(Pin1) U501.H5(RCLK) ; also on sheet 20
SD2_CLK: R1061.1 ; also on sheet 20
SD2_CMD: R1060.1 ; also on sheet 20
SD2_DATA0: R1062.1 ; also on sheet 20
SD2_DATA1: R1063.1 ; also on sheet 20
SD2_DATA2: R1064.1 ; also on sheet 20
SD2_DATA3: R1065.1 ; also on sheet 20
SD2_nCD: R1051.1 R1052.2 U1707.4(Y) ; also on sheet 20
SD2_nDET: D1004.1(A1) J1002.9(DET) R1051.2 R1054.2 TP1914.1(Pin1) U1707.2(A)
SD_CLK: D1006.1(C1) J1002.5(CLK) R1061.2
SD_CMD: D1005.1(C1) J1002.3(CMD) R1060.2
SD_DATA0: D1007.1(C1) J1002.7(DAT0) R1062.2
SD_DATA1: D1008.1(C1) J1002.8(DAT1) R1063.2
SD_DATA2: D1009.1(C1) J1002.1(DAT2) R1064.2
SD_DATA3: D1010.1(C1) J1002.2(CD/DAT3) R1065.2
STAR_I2C_SCL: J1406.3(A2) J1406.4(B2) R1443.2
STAR_I2C_SDA: J1406.5(A3) J1406.6(B3) R1445.2
SYS_nRST: C1410.1 R1427.2 ; also on sheet 5 17 19
TAMPER0: J1403.3(A2) R1431.2 R1436.1 ; also on sheet 1
TAMPER1: J1403.4(B2) R1432.2 R1437.1 ; also on sheet 1
UART1_TXD: R608.2 TP601.1(TP) ; also on sheet 5 19 20
UART2_TXD: R607.2 TP602.1(TP) ; also on sheet 5 19 20
VMIC_1V8: C1301.1 C1302.1 C1303.1 C1304.1 C1307.1 C1308.1 C1309.1 C1310.1 C1317.1 C1318.1 C1462.1 L1301.2 L1405.2 R1814.2 TP1306.1(Pin1) U1301.3(SEL) U1301.4(VDD) U1302.4(VDD) U1304.3(SEL) U1304.4(VDD) U1305.4(VDD) U1309.5(VCC)
VPCIe_3V3: L1403.1 ; also on sheet 7
VRPi_3V3: J1401.1(A1) J1401.17(A9) L1401.2 L1403.2
VRPi_5V: J1401.2(B1) J1401.4(B2) L1402.1
VSD2_3V3: C1731.1 C1732.1 D1003.1(A1) J1002.4(VDD) R1055.2 TP1919.1(Pin1) U1708.A1(VOUT)
VSD_3V3: C1020.1 R1055.1 U1708.A2(VIN) ; also on sheet 17
N112168459: R1402.2 U1401.12(CS)
N112168530: TP1402.1(Pin1) U1401.11(SDO_AUX)
N112168572: R1409.2 U1401.1(SDO/SA0)
N112168574: TP1403.1(Pin1) U1401.10(OCS_AUX)
N112168590: R1410.2 U1401.2(SDX)
N112168603: R1412.2 U1401.3(SCX)
N112168605: TP1404.1(Pin1) U1401.9(INT2)
N112168607: D1401.C(CATHODE) R1420.2 U1401.4(INT1)
N112179037: J1401.37(A19) J1710.2
N112179124: J1401.36(B18) R856.1
N112179125: J1401.12(B6) R855.1
N112179128: J1401.16(B8) R853.1
N113364863: J1405.6(B3) J1405.8(B4) R1444.1
N113365543: J1405.3(A2) R1440.2 R1446.1
N113365548: J1405.5(A3) R1441.2 R1447.1
N113409056: R1426.1 SW1401.3(B1) SW1401.4(B2)
N113409060: R1427.1 SW1402.3(B1) SW1402.4(B2)
N114502549: R1703.2 U1702.2(D1)
N114502556: R1704.2 U1702.5(D2)
N114502597: R1705.2 U1702.7(D3)
N114797754: D1402.4(CATHODE3) R1423.1
N114797756: D1402.3(CATHODE2) R1424.1
N114797758: D1402.1(CATHODE1) R1425.1
N114798676: Q1403.1(GATE) R1435.1 R1439.2
N114798680: Q1401.1(GATE) R1434.1 R1438.2
N114800112: Q1402.1(GATE) R1429.2 R1433.1
N115329910: J1401.15(A8) R854.2
N115331791: J1405.2(B1) J1405.4(B2) R1442.1
N115688375: R1057.2 U1708.B2(ON)
N115754842: J1405.7(A4) R1448.1
N115782425: C1321.1 C1322.1 C1323.1 R1329.1 R1814.1 U1306.5(OUT)
N115782532: C1321.2 R1329.2 R1330.1 U1306.4(NC)
N115782544: R1333.2 U1306.3(EN)
N115782790: R1302.1 U1301.1(DAT)
N115782792: R1302.2 R1303.2 U1307.2(A)
N115782811: R1324.1 R1325.1 R1326.1 R1327.1 U1309.4(Y)
N115782815: R1324.2 U1301.2(CLK)
N115783013: R1303.1 U1302.1(DAT)
N115783041: R1325.2 U1302.2(CLK)
N115783217: R1318.1 U1304.1(DAT)
N115783219: R1318.2 R1322.2 U1308.2(A)
N115783240: R1326.2 U1304.2(CLK)
N115783428: R1322.1 U1305.1(DAT)
N115783445: R1327.2 U1305.2(CLK)
N115785368: R601.2 SW601.2
N115785370: R602.2 SW601.4
N115785372: R603.2 SW601.6
N115785374: R604.2 SW601.8
N115837191: TP504.1(Pin1) U501.K5(~{RST})
N116227167: J1710.1 R745.1
N116439658: R1824.1 R1825.2 U1714.4(EN)
N116441929: R1827.2 TP45.1(Pin1) U58.3(FLG)
N116441950: C10.1 R14.1 R16.2 U58.4(EN)

Not connected (* = marked no-connect by the designer): U501 A1(NC)* A2(NC)* A7(NC)* A8(NC)* A9(NC)* A10(NC)* A11(NC)* A12(NC)* A13(NC)* A14(NC)* B1(NC)* B7(NC)* B8(NC)* B9(NC)* B10(NC)* B11(NC)* B12(NC)* B13(NC)* B14(NC)* C1(NC)* C3(NC)* C5(NC)* C7(NC)* C8(NC)* C9(NC)* C10(NC)* C11(NC)* C12(NC)* C13(NC)* C14(NC)* D1(NC)* D2(NC)* D3(NC)* D4(NC)* D12(NC)* D13(NC)* D14(NC)* E1(NC)* E2(NC)* E3(NC)* E5(NC)* E8(NC)* E9(VSF1)* E10(VSF2)* E12(NC)* E13(NC)* E14(NC)* F1(NC)* F2(NC)* F3(NC)* F10(VSF3)* F12(NC)* F13(NC)* F14(NC)* G1(NC)* G2(NC)* G3(NC)* G10(NC)* G12(NC)* G13(NC)* G14(NC)* H1(NC)* H2(NC)* H3(NC)* H12(NC)* H13(NC)* H14(NC)* J1(NC)* J2(NC)* J3(NC)* J12(NC)* J13(NC)* J14(NC)* K1(NC)* K2(NC)* K3(NC)* K6(NC)* K7(NC)* K10(VSF4)* K12(NC)* K13(NC)* K14(NC)* L1(NC)* L2(NC)* L3(NC)* L12(NC)* L13(NC)* L14(NC)* M1(NC)* M2(NC)* M3(NC)* M7(NC)* M8(NC)* M9(NC)* M10(NC)* M11(NC)* M12(NC)* M13(NC)* M14(NC)* N1(NC)* N3(NC)* N6(NC)* N7(NC)* N8(NC)* N9(NC)* N10(NC)* N11(NC)* N12(NC)* N13(NC)* N14(NC)* P1(NC)* P2(NC)* P7(NC)* P8(NC)* P9(NC)* P10(NC)* P11(NC)* P12(NC)* P13(NC)* P14(NC)*; U1307 1(NC)*; U1308 1(NC)*; U1309 1(NC)*; U1702 10(D4)* 11(S4B)* 12(S4A)*

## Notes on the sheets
sheet 21
- IMU:
- Accelerometer/Gyroscope (w/o eCompass)
- EXPI
- VDD: 1.71V-3.6V
  VDD_IO: 1.62V-3.6V
- #I3C SUPPORT
- GPIO2_I2C4.SDA
- GPIO3_I2C4.SCL
- GPIO4_PDM.CLK
- GPIO14_UART3.TX
- GPIO15_UART3.RX
- GPIO17_SAI3_MCLK
- GPIO18_SAI3.RXBCLK
- GPIO27_PUSHBUTTON_INT
- GPIO22_SPDIF_IN
- GPIO23_SPDIF_OUT
- GPIO24_DC_INT
- GPIO10_SPI3.SOUT
- Default: output forced to ground
- GPIO9_SPI3.SIN
- GPIO25_DC_RESET
- GPIO11_SPI3.SCK
- GPIO8_SPI3.CS0
- GPIO00_MIC_MUTE_INT
- DC_GPIO1
- GPIO7_SPI3.CS1
- GPIO05_PDM_BITSTREAM_0
- GPIO06_PDM_BITSTREAM_1
- GPIO12_PDM_BITSTREAM
- GPIO13_PDM_BITSTREAM_3
- GPIO19_SAI3.RXSYNC
- GPIO16_SAI3.TXBCLK
- GPIO26_SAI3.TXSYNC
- GPIO20_SAI3.RXDATA0
- #I2C ADDR: 0b'110101[0]x
- GPIO21_SAI3.TXDATA0
- Default: input with pull-down
- Push-pull/open-drain selection on INT1 and INT2 pins. Default value: 0
  (0: push-pull mode; 1: open-drain mode)
- INT1 pin floating (internal pull-down): I2C/I3C both active
  INT1 pin connected to VDD_IO: only I3C active
- No TXSYNC on IMX93 9x9 chip
  When Audio Hat Board  is connected,short J1710
- 2.7 V to 5.5 V / 2A
- TAMPER
- RGB LED w/ PWM
- 2.7 V to 5.5 V / 3A
- I2C CN
- ADC x2 CH
- # Prevent PWR SEQ violation from ADC port
- Buttons
sheet 22
- FLASH: eMMC <5.1>
- 16GB <2D MLC eMMC>
- NOTE:
- All the CAPs in this page need to be put on the bottom of BGA,
  and close the PINs as short as possible.
- OE
- A
- Y
- NOTE
- H
- H
- H
- Normal Operation, No card detected
- H
- L
- L
- Normal Operation, card insert
- L
- L
- H
- L
- H
- H
- No card at slot
- Simulation, card plug-out
- MicroSD 3.0
- Only used for SD card Plug-in/out Simulation, Remove this
  circuits and install R1051/R1055 if test not required.
- 74LV1T126GVH is level translating buffer/line driver
  with 3-state output
- # Push-Push
sheet 23
- BOOT MODE CFG
- PDM MIC
- LDO 1.8V for DMIC
- 450mA@0.45V Drop
- VIN: 1.2V-5.5V
- LDO
- R1
- i.MX93 BOOT MODE
- Vfb=0.8V
- R2
- DIS CHG: 280 0HM
- BOOT_MODE[3:0]
- BOOT CORE
- BOOT DEVICE
- COMMENT
- Vout=(1+R1/R2)*Vfb
- 0000
  0001
  0010
  0011
  0100
  0101
  0110
  0111
  1000
  1001
  1010
  1011
  1100
  1101
  1110
  1111
- Cortex-A55
  Cortex-A55
  Cortex-A55
  Cortex-A55
  Cortex-A55
  Cortex-A55
  Cortex-A55
  Cortex-A55
  Cortex-M33
  Cortex-M33
  Cortex-M33
  Cortex-M33
  Cortex-M33
  Cortex-M33
  Cortex-M33
  Cortex-M33
- From internal fuses
  Serial Downloader(USB1)
  USDHC1 8-bit eMMC 5.1
  USDHC2 4-bit SD3.0
  FlexSPI Serial NOR
  FlexSPI Serial NAND 2K
  Infinite Loop
  Test Mode (A55)
  LPB: Boot From Fuses
  LPB: Serial Downloader (USB1)
  LPB: USDHC1 8-bit 1.8V eMMC 5.1
  LPB: USDHC2 4-bit SD 3.0
  LPB: FlexSPI Serial NOR
  LPB: FlexSPI Serial NAND 2K
  Infinite Loop
  Test Mode (For DFT ATE Test)
- USB1
  with SFDP (JESD-216) discoverable parameters
  USB1
  with SFDP (JESD-216) discoverable parameters
- # FB = 0.8V
- # 1.80V: R1/R2 = 1.0/0.8 : 15K/12K
- Sec SRC:
  150mA:   LDCL015MR (ADJ)
  300mA:   RT9078N-08GJ5
  350mA:   UM1750S-18
  450mA:   NCP161ASN180T1G
- 300mA:   RT9078N-08GJ5
  350mA:   UM1750S-18
  450mA:   NCP161ASN180T1G
- MIC/CAN
- BOOT CFG
- #DIP SW [3:0]:
- 0001 <Serial DL>
  0010 <eMMC>
  0011 <SD3.0>
- BMODE OVER DRV
- #BOOT_MODE3
- #BOOT_MODE2
- #BOOT_MODE1
- #BOOT_MODE0
- #SoC PU/PD:
        27K-32K-38K <MIN-TYP-MAX>
- 74LV1T34GWH:
        Used for 1.8V/3.3V level translator;
        Both 1.8V and 3.3V can be used for the DMIC array;
        1.8V is designed due to high SNR;
        If 3.3V used,  part can be removed;
